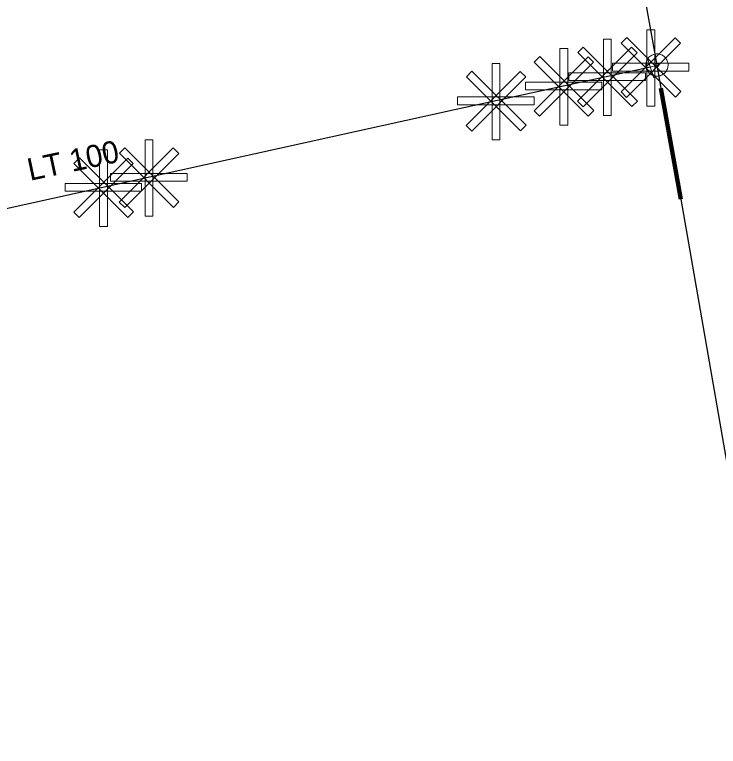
# Model space of a CAD drawing. Extents: x -809028 to -807737, y -990545 to -989489.
# Drawn here: x -807904.21 to -807872.6, y -990078.33 to -990045.44 of the extents above; entities that cross this region are included whole.
import ezdxf

# ---------------------------------------------------------------- set-up
doc = ezdxf.new("R2010")
doc.units = 0
doc.header["$LTSCALE"] = 0.32
for name, color, linetype, lineweight in [('1', 7, 'Continuous', 13), ('12', 7, 'Continuous', 13), ('14', 7, 'Continuous', 25), ('17', 7, 'Continuous', 25), ('3', 7, 'Continuous', 106), ('34', 7, 'Continuous', 13), ('47', 7, 'Continuous', 13)]:
    doc.layers.add(name, color=color, linetype=linetype, lineweight=lineweight)

msp = doc.modelspace()

# ---------------------------------------------------------------- linework, layer by layer
at = {"layer": '12'}
for points in [[(-807875.807, -990046.122), (-807875.456, -990046.122), (-807875.456, -990049.557), (-807875.807, -990049.557)], [(-807877.761, -990046.547), (-807877.411, -990046.547), (-807877.411, -990049.982), (-807877.761, -990049.982)], [(-807874.541, -990046.486), (-807874.293, -990046.734), (-807876.722, -990049.163), (-807876.968, -990048.915)], [(-807876.96, -990046.725), (-807876.713, -990046.477), (-807874.284, -990048.906), (-807874.531, -990049.154)], [(-807876.495, -990046.911), (-807876.247, -990047.159), (-807878.676, -990049.588), (-807878.923, -990049.34)], [(-807878.914, -990047.15), (-807878.667, -990046.902), (-807876.238, -990049.331), (-807876.485, -990049.579)], [(-807879.717, -990046.973), (-807879.367, -990046.973), (-807879.367, -990050.408), (-807879.717, -990050.408)], [(-807878.451, -990047.337), (-807878.203, -990047.585), (-807880.632, -990050.014), (-807880.879, -990049.766)], [(-807880.87, -990047.576), (-807880.623, -990047.328), (-807878.194, -990049.757), (-807878.441, -990050.005)], [(-807882.763, -990047.635), (-807882.413, -990047.635), (-807882.413, -990051.07), (-807882.763, -990051.07)], [(-807873.923, -990047.631), (-807873.923, -990047.981), (-807877.358, -990047.981), (-807877.358, -990047.631)], [(-807881.497, -990047.999), (-807881.249, -990048.247), (-807883.678, -990050.676), (-807883.924, -990050.428)], [(-807883.916, -990048.238), (-807883.669, -990047.99), (-807881.24, -990050.419), (-807881.487, -990050.667)], [(-807875.877, -990048.056), (-807875.877, -990048.406), (-807879.312, -990048.406), (-807879.312, -990048.056)], [(-807877.833, -990048.482), (-807877.833, -990048.832), (-807881.268, -990048.832), (-807881.268, -990048.482)], [(-807880.879, -990049.144), (-807880.879, -990049.494), (-807884.314, -990049.494), (-807884.314, -990049.144)], [(-807898.353, -990051.075), (-807898.002, -990051.075), (-807898.002, -990054.51), (-807898.353, -990054.51)], [(-807900.398, -990051.527), (-807900.048, -990051.527), (-807900.048, -990054.962), (-807900.398, -990054.962)], [(-807897.087, -990051.439), (-807896.838, -990051.687), (-807899.267, -990054.116), (-807899.514, -990053.868)], [(-807899.505, -990051.678), (-807899.259, -990051.43), (-807896.83, -990053.859), (-807897.076, -990054.107)], [(-807899.132, -990051.891), (-807898.884, -990052.139), (-807901.313, -990054.568), (-807901.559, -990054.32)], [(-807901.551, -990052.13), (-807901.304, -990051.882), (-807898.875, -990054.311), (-807899.122, -990054.559)], [(-807896.468, -990052.584), (-807896.468, -990052.934), (-807899.904, -990052.934), (-807899.904, -990052.584)], [(-807898.514, -990053.036), (-807898.514, -990053.386), (-807901.949, -990053.386), (-807901.949, -990053.036)]]:
    msp.add_lwpolyline(points, close=True, dxfattribs=at)
at = {"layer": '14', "lineweight": 13}
msp.add_line((-807875.358, -990047.71), (-807875.649, -990047.807), dxfattribs=at)
at = {"layer": '17'}
for points in [[(-807890.584, -989975.818), (-807887.359, -989987.813), (-807883.691, -990001.375), (-807875.358, -990047.71)], [(-807875.649, -990047.807), (-807884.375, -990049.706), (-807925.101, -990058.706), (-807923.331, -990070.607), (-807924.262, -990070.824)], [(-807875.358, -990047.71), (-807875.182, -990048.745), (-807874.291, -990053.739), (-807870.006, -990078.335)]]:
    msp.add_lwpolyline(points, dxfattribs=at)
at = {"layer": '3'}
msp.add_line((-807875.183, -990048.745), (-807874.291, -990053.74), dxfattribs=at)
at = {"layer": '3', "lineweight": 100}
msp.add_line((-807875.183, -990048.745), (-807874.291, -990053.74), dxfattribs=at)
at = {"layer": '34'}
msp.add_line((-807875.807, -990047.332), (-807875.491, -990048.281), dxfattribs=at)
at = {"layer": '47'}
for points in [[(-807875.269, -990048.202), (-807875.218, -990048.189), (-807875.169, -990048.172), (-807875.122, -990048.15), (-807875.077, -990048.123), (-807875.035, -990048.091), (-807874.997, -990048.055), (-807874.963, -990048.016), (-807874.933, -990047.973), (-807874.908, -990047.927), (-807874.887, -990047.879), (-807874.872, -990047.828), (-807874.863, -990047.777), (-807874.858, -990047.725), (-807874.859, -990047.673), (-807874.865, -990047.621), (-807874.878, -990047.57), (-807874.895, -990047.521), (-807874.917, -990047.473), (-807874.944, -990047.429), (-807874.976, -990047.387), (-807875.012, -990047.349), (-807875.052, -990047.314), (-807875.095, -990047.284), (-807875.14, -990047.259), (-807875.188, -990047.239), (-807875.239, -990047.224), (-807875.29, -990047.214), (-807875.342, -990047.21), (-807875.394, -990047.211), (-807875.446, -990047.217), (-807875.497, -990047.23), (-807875.546, -990047.247), (-807875.594, -990047.268), (-807875.638, -990047.296), (-807875.68, -990047.328), (-807875.719, -990047.363), (-807875.753, -990047.403), (-807875.783, -990047.446), (-807875.808, -990047.492), (-807875.828, -990047.54), (-807875.843, -990047.591), (-807875.853, -990047.641), (-807875.857, -990047.694), (-807875.856, -990047.746), (-807875.85, -990047.798), (-807875.837, -990047.849), (-807875.82, -990047.898), (-807875.799, -990047.945), (-807875.771, -990047.99), (-807875.739, -990048.032), (-807875.704, -990048.071), (-807875.665, -990048.104), (-807875.622, -990048.134), (-807875.575, -990048.159), (-807875.527, -990048.18), (-807875.476, -990048.195), (-807875.426, -990048.204), (-807875.373, -990048.209), (-807875.321, -990048.208)], [(-807875.343, -990047.79), (-807875.334, -990047.789), (-807875.327, -990047.785), (-807875.319, -990047.782), (-807875.312, -990047.777), (-807875.305, -990047.772), (-807875.299, -990047.766), (-807875.293, -990047.76), (-807875.288, -990047.753), (-807875.284, -990047.745), (-807875.28, -990047.737), (-807875.278, -990047.729), (-807875.276, -990047.72), (-807875.276, -990047.712), (-807875.275, -990047.704), (-807875.277, -990047.695), (-807875.278, -990047.686), (-807875.282, -990047.679), (-807875.285, -990047.671), (-807875.29, -990047.664), (-807875.295, -990047.657), (-807875.301, -990047.651), (-807875.307, -990047.645), (-807875.314, -990047.64), (-807875.322, -990047.635), (-807875.33, -990047.632), (-807875.338, -990047.63), (-807875.347, -990047.628), (-807875.355, -990047.628), (-807875.363, -990047.627), (-807875.372, -990047.629), (-807875.381, -990047.63), (-807875.388, -990047.634), (-807875.396, -990047.637), (-807875.403, -990047.642), (-807875.41, -990047.647), (-807875.417, -990047.652), (-807875.422, -990047.659), (-807875.427, -990047.666), (-807875.432, -990047.674), (-807875.435, -990047.682), (-807875.437, -990047.69), (-807875.439, -990047.699), (-807875.439, -990047.707), (-807875.44, -990047.715), (-807875.438, -990047.724), (-807875.437, -990047.733), (-807875.433, -990047.74), (-807875.43, -990047.748), (-807875.425, -990047.755), (-807875.42, -990047.762), (-807875.415, -990047.769), (-807875.408, -990047.774), (-807875.401, -990047.779), (-807875.393, -990047.783), (-807875.385, -990047.787), (-807875.377, -990047.789), (-807875.368, -990047.791), (-807875.36, -990047.791), (-807875.352, -990047.792)]]:
    msp.add_lwpolyline(points, close=True, dxfattribs=at)

# ---------------------------------------------------------------- texts
at = {"layer": '1'}
msp.add_text('LT 100', height=1, rotation=12, dxfattribs=at).set_placement((-807903.522, -990052.917))

doc.saveas('drawing.dxf')
